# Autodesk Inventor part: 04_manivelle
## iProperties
Created: 2002-11
Part Number: 04_manivelle
Material: Acier doux
Document SubType Name: Modélisation
Designer: poste-2
Control State: 0
Master: False
Checked Out: False
Shininess: 21.0
Length Units: 11269
Angle Units: 11279
Time Units: 11290
Mass Units: 11283
Length Display Precision: 3
Angle Display Precision: 2
Compacted: True
Density: 7.86
Volumn: 1.6273607321365955
Area: 12.205832931423576
PropertySet Name: Model Information
Author: poste-2
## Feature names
1. Extrusion1
